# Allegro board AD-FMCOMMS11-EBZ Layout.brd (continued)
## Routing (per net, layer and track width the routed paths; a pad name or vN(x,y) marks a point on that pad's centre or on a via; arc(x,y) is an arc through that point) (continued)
UNNAMED_22_CAP_I380_N1: length 4.2
  BOTTOM w0.203: R89.2 C71.1 51.55,34.89 53.21,34.89 53.49,34.61 Q4.4
UNNAMED_22_CAP_I380_N2: length 5.3
  BOTTOM w0.305: 53.85,33.24 52.2,33.24 C71.2
  BOTTOM w0.406: 54.81,33.49 Q4.2 ; 55.47,33.49 Q4.1 ; 54.15,33.49 Q4.3
UNNAMED_23_AD9625_I119_SYSREF: length 1
  TOP w0.254: U101.K14 v1(55.21,56.09)
  BOTTOM w0.254: v1(55.21,56.09) 55.24,56.06 C105.1
UNNAMED_23_AD9625_I119_SYSREF_1: length 1.1
  TOP w0.254: U101.J14 v1(54.41,56.04)
  BOTTOM w0.254: v1(54.41,56.04) 54.48,55.97 C141.1
UNNAMED_25_ADHMC1119_I179_ATTIN: length 0.3
  TOP w0.686: 25.98,50.63 C323.2
UNNAMED_25_ADHMC1119_I179_ATTOU: length 1.7
  TOP w0.203: C324.1 32.69,50.64 U25.14
UNNAMED_25_ADHMC1119_I179_P: length 1.5
  TOP w0.254: R137.2 26.19,52.22 26.77,51.65 U25.3
UNNAMED_25_CAP_I165_N1: length 1.9
  TOP w0.203: C318.1 40.51,51.22 40,50.71 T5.6
UNNAMED_25_CAP_I165_N2: length 0.8
  TOP w0.203: R57.1 C318.2
UNNAMED_25_CAP_I166_N1: length 1.9
  TOP w0.203: T5.4 40,53.25 40.51,52.74 C319.1
UNNAMED_25_CAP_I166_N2: length 0.8
  TOP w0.203: R58.1 C319.2
UNNAMED_25_CAP_I167_N2: length 3.9
  TOP w0.203: 43.74,51.98 43.74,52.09 R60.1 ; 43.74,51.98 43.74,51.87 R59.2 ; 43.74,51.98 C320.2 ; 43.74,51.98 43.87,51.98 ; R59.2 44.15,51.87 44.15,51.98 ; R59.2 43.94,51.9 ; R60.1 44.15,52.09 44.15,51.98 ; R60.1 43.94,51.9 ; 43.94,51.9 43.87,51.98 ; 44.15,51.98 R61.1 ; 44.15,51.98 43.87,51.98
UNNAMED_25_CAP_I186_N2: length 3.1
  TOP w0.203: T5.1 36.31,50.63 C324.2
UNNAMED_25_CAP_I188_N1: length 23.4
  TOP w0.686: J6.1 C323.1
UNNAMED_25_RES_I158_N1: length 1.6
  TOP w0.203: R62.1 44.32,51.03 R59.1 43.75,51.22 R57.2
UNNAMED_25_RES_I159_N2: length 1.7
  TOP w0.203: R58.2 43.75,52.74 R60.2 44.45,52.93 R63.1
UNNAMED_26_ADM7154_I174_BYP: length 1.9
  TOP w0.203: v3(62.99,35.52) 63.37,35.65 U20.3
  BOTTOM w0.305: v3(62.99,35.52) 62.99,36.27 C245.2
UNNAMED_26_ADM7154_I174_REF: length 2.9
  TOP w0.203: 68.17,35.15 C248.1 ; 68.17,35.15 68.17,35.29 67.81,35.65 U20.6 ; 68.17,35.15 U20.5
UNNAMED_26_ADM7154_I174_VOUT: length 8.7
  TOP w0.305: U20.2 63,36.15
  TOP w0.635: 55.88,34.53 E29.1 56.87,35.46 ; 58.93,34.53 E28.1 ; E28.1 59.92,35.46 ; E28.1 57.94,35.46
  TOP w0.762: 60.9,36.37 C250.1 ; C250.1 62.8,36.37 ; C250.1 61.85,37.27
UNNAMED_26_ADM7154_I174_VREG: length 2.3
  TOP w0.305: U20.1 64.08,38.66 C247.1
UNNAMED_26_ADP1741_I5_ADJ: length 3.1
  TOP w0.203: v3(80.64,64.98) 81.07,64.56 VR2.9
  BOTTOM w0.203: R119.1 v3(80.64,64.98) 80.66,65 R114.1
UNNAMED_26_ADP1741_I5_PG: length 4.3
  TOP w0.203: VR2.5 84.67,66.53 85.03,66.89 R75.2 86.93,66.13 R120.2
UNNAMED_26_ADP1741_I5_SS: length 1.6
  TOP w0.203: C226.1 83.37,66.52 VR2.7
UNNAMED_26_ADP1741_I5_VOUT: length 11
  TOP w0.305: 82.18,61.69 VR2.13 82.72,60.81 ; 80.92,62.61 VR2.12 81.79,62.08 ; 83.37,60.81 VR2.14 ; 80.92,63.91 VR2.10 ; 80.92,63.26 VR2.11
  TOP w0.635: C228.1 79.88,62.04 ; C228.1 80.84,61.14 ; C228.1 78.93,61.14 ; 79.44,63.1 E23.1 80.37,64.1
  BOTTOM w0.305: v3(80.64,62.32) R119.2
UNNAMED_26_ADP1741_I121_ADJ: length 3.3
  TOP w0.203: v3(73.66,59.4) R117.1 R113.1
  BOTTOM w0.305: VR1.9 73.24,59.56 73.41,59.4 v3(73.66,59.4)
UNNAMED_26_ADP1741_I121_PG: length 2.9
  BOTTOM w0.203: R72.2 76.33,64.29 R118.2
  BOTTOM w0.305: VR1.5 75.02,63.29 75.56,63.84 R118.2
UNNAMED_26_ADP1741_I121_SS: length 1.4
  BOTTOM w0.203: VR1.7 75.56,61.99 C207.1
UNNAMED_26_ADP1741_I121_VOUT: length 9.9
  TOP w0.508: R117.2 v3(70.74,59.4)
  BOTTOM w0.635: C227.1 71.95,58.22 ; C227.1 70.99,59.12 ; C227.1 70.04,58.22
  BOTTOM w0.762: 68.39,60.51 E24.1 69.32,59.52
  BOTTOM w1.016: E25.1 E24.1
UNNAMED_26_ADP1741_I139_ADJ: length 2.7
  TOP w0.305: R122.1 R121.1 37.34,47.57 v3(37.33,47.58)
  BOTTOM w0.203: VR3.9 v3(37.33,47.58)
UNNAMED_26_ADP1741_I139_PG: length 2.9
  BOTTOM w0.203: 34.46,49.31 34.28,49.49 34.29,49.5 R76.2 ; 34.46,49.31 34.46,49.31 R126.2 ; 34.46,49.31 VR3.5
UNNAMED_26_ADP1741_I139_SS: length 1.7
  BOTTOM w0.203: C246.1 35.75,47.84 VR3.7
UNNAMED_26_ADP1741_I139_VOUT: length 10.6
  TOP w0.305: R122.2 38.48,44.66 v3(38.23,44.41)
  BOTTOM w0.305: 36.94,44.03 VR3.13 36.41,43.16 ; VR3.11 38.21,45.61 ; 38.21,44.96 VR3.12 37.33,44.43 ; VR3.10 38.21,46.26 ; 35.76,43.16 VR3.14
  BOTTOM w0.635: 38.42,45.85 C249.1 39.37,44.94
  BOTTOM w0.762: 39.31,44.39 E30.1 38.38,43.39
UNNAMED_27_CAP_I362_N2: length 2.1
  TOP w0.254: v1(98.37,57.29) 98.37,56.77 98.11,56.51 97.64,56.51 C208.2
  BOTTOM w0.254: P1.A2 v1(98.37,57.29)
UNNAMED_27_CAP_I363_N2: length 3
  TOP w0.254: v1(99.08,57.29) 98.82,57.04 98.82,56.58 98.3,56.06 97.64,56.06 C209.2
  BOTTOM w0.254: P1.A3 v1(99.08,57.29)
UNNAMED_27_CAP_I364_N2: length 3.2
  TOP w0.254: C211.2 97.64,50.72 98.23,50.72 98.93,51.41 98.93,52.06 v1(99.08,52.21)
  BOTTOM w0.254: P1.A7 v1(99.08,52.21)
UNNAMED_27_CAP_I365_N2: length 2.4
  TOP w0.254: v1(98.37,52.21) 98.47,52.11 98.47,51.6 98.04,51.18 97.64,51.18 C210.2
  BOTTOM w0.254: P1.A6 v1(98.37,52.21)
UNNAMED_27_CAP_I366_N2: length 3.2
  TOP w0.254: v1(99.08,47.13) 98.82,46.88 98.82,46.21 98.26,45.64 97.64,45.64 C213.2
  BOTTOM w0.254: P1.A11 v1(99.08,47.13)
UNNAMED_27_CAP_I367_N2: length 2.4
  TOP w0.254: v1(98.37,47.13) 98.37,46.4 98.07,46.1 97.64,46.1 C212.2
  BOTTOM w0.254: P1.A10 v1(98.37,47.13)
UNNAMED_27_CAP_I368_N2: length 2.5
  TOP w0.254: v1(98.37,42.05) 98.5,41.92 98.5,41.45 98.07,41.02 97.64,41.02 C214.2
  BOTTOM w0.254: P1.A14 v1(98.37,42.05)
UNNAMED_27_CAP_I369_N2: length 3.2
  TOP w0.254: v1(99.08,42.05) 98.96,41.93 98.96,41.26 98.26,40.56 97.64,40.56 C215.2
  BOTTOM w0.254: P1.A15 v1(99.08,42.05)
UNNAMED_27_CAP_I370_N2: length 2.4
  TOP w0.254: C216.2 97.64,35.94 98.07,35.94 98.37,36.24 v1(98.37,36.97)
  BOTTOM w0.254: P1.A18 v1(98.37,36.97)
UNNAMED_27_CAP_I371_N2: length 3.2
  TOP w0.254: C217.2 97.64,35.48 98.26,35.48 98.82,36.05 98.82,36.72 v1(99.08,36.97)
  BOTTOM w0.254: P1.A19 v1(99.08,36.97)
UNNAMED_27_CAP_I373_N2: length 3.2
  TOP w0.254: v1(97.81,44.59) 97.55,44.34 97.55,43.77 96.89,43.1 96.37,43.1 C219.2
  BOTTOM w0.254: P1.B13 v1(97.81,44.59)
UNNAMED_27_CAP_I374_N2: length 2.3
  TOP w0.254: C218.2 96.37,43.56 96.7,43.56 97.1,43.96 v1(97.1,44.59)
  BOTTOM w0.254: P1.B12 v1(97.1,44.59)
UNNAMED_27_CAP_I375_N2: length 2.4
  TOP w0.254: C220.2 96.37,38.48 96.8,38.48 97.1,38.78 v1(97.1,39.51)
  BOTTOM w0.254: P1.B16 v1(97.1,39.51)
UNNAMED_27_CAP_I376_N2: length 3.2
  TOP w0.254: C221.2 96.37,38.02 96.99,38.02 97.55,38.59 97.55,39.26 v1(97.81,39.51)
  BOTTOM w0.254: P1.B17 v1(97.81,39.51)
UNNAMED_27_CAP_I377_N2: length 3.5
  TOP w0.254: C223.2 97.28,53.97 96.7,53.97 96.08,53.36 96.08,52.47 v1(95.83,52.21)
  BOTTOM w0.254: P1.C7 v1(95.83,52.21)
UNNAMED_27_CAP_I378_N2: length 2.6
  TOP w0.254: C222.2 97.28,53.52 96.89,53.52 96.54,53.17 v1(96.54,52.21)
  BOTTOM w0.254: P1.C6 v1(96.54,52.21)
UNNAMED_27_CAP_I461_N2: length 2.6
  TOP w0.254: v1(98.37,31.89) 98.5,31.76 98.5,31.13 98.21,30.83 97.64,30.83 C165.2
  BOTTOM w0.254: P1.A22 v1(98.37,31.89)
UNNAMED_27_CAP_I462_N2: length 3.3
  TOP w0.254: v1(99.08,31.89) 98.96,31.77 98.96,30.94 98.4,30.38 97.64,30.38 C166.2
  BOTTOM w0.254: P1.A23 v1(99.08,31.89)
UNNAMED_27_CAP_I463_N2: length 1.5
  TOP w0.254: C167.2 98.71,21.95 99.24,21.95 v1(99.38,22.09)
  BOTTOM w0.254: P1.A30 v1(99.38,22.09)
UNNAMED_27_CAP_I464_N2: length 1.5
  TOP w0.254: v1(99.38,21.38) 99.27,21.49 98.71,21.49 C168.2
  BOTTOM w0.254: P1.A31 v1(99.38,21.38)
UNNAMED_27_CAP_I465_N2: length 2.9
  TOP w0.254: v1(97.1,14.11) 97.35,14.37 97.35,14.77 96.95,15.18 96.13,15.18 C179.2
  BOTTOM w0.254: 97.45,14.75 v1(97.1,14.11)
UNNAMED_27_CAP_I466_N2: length 3.6
  TOP w0.254: v1(97.81,14.11) 97.81,14.96 97.13,15.64 96.13,15.64 C180.2
  BOTTOM w0.254: 97.45,13.48 v1(97.81,14.11)
UNNAMED_27_CAP_I467_N2: length 2.9
  TOP w0.254: v1(98.37,11.57) 98.62,11.83 98.62,12.23 98.22,12.64 97.4,12.64 C169.2
  BOTTOM w0.254: P1.A38 v1(98.37,11.57)
UNNAMED_27_CAP_I468_N2: length 3.6
  TOP w0.254: C170.2 97.4,13.1 98.4,13.1 99.08,12.42 v1(99.08,11.57)
  BOTTOM w0.254: P1.A39 v1(99.08,11.57)
UNNAMED_27_CAP_I469_N2: length 2.7
  TOP w0.254: v1(97.1,19.19) 97.33,19.42 97.33,19.6 96.86,20.07 96.09,20.07 C171.2
  BOTTOM w0.254: 97.45,19.83 v1(97.1,19.19)
UNNAMED_27_CAP_I470_N2: length 3.4
  TOP w0.254: C172.2 96.08,20.53 97.05,20.53 97.78,19.79 97.78,19.24 97.81,19.21 v1(97.81,19.19)
  BOTTOM w0.254: 97.45,18.56 v1(97.81,19.19)
UNNAMED_27_CAP_I471_N2: length 2.8
  TOP w0.254: v1(98.37,16.65) 98.6,16.88 98.6,17.06 97.77,17.89 97.4,17.89 C177.2
  BOTTOM w0.254: P1.A34 v1(98.37,16.65)
UNNAMED_27_CAP_I472_N2: length 3.5
  TOP w0.254: C178.2 97.4,18.34 97.96,18.34 99.05,17.25 99.05,16.7 99.08,16.67 v1(99.08,16.65)
  BOTTOM w0.254: P1.A35 v1(99.08,16.65)
UNNAMED_27_CAP_I473_N2: length 1.4
  TOP w0.254: C176.2 98.77,26.57 99.27,26.57 v1(99.38,26.46)
  BOTTOM w0.254: P1.A27 v1(99.38,26.46)
UNNAMED_27_CAP_I474_N2: length 1.4
  TOP w0.254: C175.2 98.77,27.03 99.24,27.03 v1(99.38,27.17)
  BOTTOM w0.254: P1.A26 v1(99.38,27.17)
UNNAMED_27_CAP_I475_N2: length 13.4
  BOTTOM w0.254: P1.C3 96.18,56.65 95.62,56.09 86.92,56.09 86.58,56.43 85.04,56.43 84.32,55.71 84.32,55.13 84.5,54.96 C174.2
UNNAMED_27_CAP_I476_N2: length 14.2
  BOTTOM w0.254: C173.2 83.86,55.9 84.85,56.89 86.64,56.89 87.11,57.36 95.62,57.36 96.18,57.92 P1.C2
UNNAMED_27_CAP_I499_N2: length 2.4
  TOP w0.127: v1(94.56,54.75) 94.74,54.57 94.74,53.94 94.6,53.8 94.25,53.8 94.24,53.81 94.23,53.81 C239.2
  BOTTOM w0.127: P1.D4 v1(94.56,54.75)
UNNAMED_27_CAP_I500_N2: length 2.8
  TOP w0.127: C240.2 94.25,53.54 94.71,53.54 95,53.83 95,54.48 v1(95.27,54.75)
  BOTTOM w0.127: P1.D5 v1(95.27,54.75)
UNNAMED_27_CAP_I501_N2: length 3.7
  TOP w0.127: v1(97.92,34.38) 97.59,34.05 97.59,33.61 97.16,33.18 96.04,33.18 C32.2
  BOTTOM w0.127: 97.45,35.07 v1(97.92,34.38)
UNNAMED_27_CAP_I502_N2: length 3.2
  TOP w0.127: C34.2 95.88,33.62 96.06,33.44 97.05,33.44 97.33,33.72 97.33,34.07 v1(97.03,34.38)
  BOTTOM w0.127: 97.45,33.8 97.03,34.36 v1(97.03,34.38)
UNNAMED_27_CN400PAKV2_I437_TDI: length 1.3
  BOTTOM w0.254: 94.91,22.37 94.91,21.1
UNNAMED_27_CN400PAKV2_I439_LA03: length 4
  TOP w0.127: R81.2 88.87,49.25 89.07,49.44 90.8,49.44 90.93,49.31 90.93,48.59 v1(90.75,48.4)
  BOTTOM w0.127: P1.G10 v1(90.75,48.4)
UNNAMED_27_CN400PAKV2_I439_LA_1: length 4.3
  TOP w0.127: v1(91.46,48.4) 91.19,48.68 91.19,49.42 90.91,49.69 89.01,49.69 R80.2
  BOTTOM w0.127: P1.G9 v1(91.46,48.4)
UNNAMED_28_ADF4355_I1290_CPOUT: length 3.7
  BOTTOM w0.203: U18.7 39.35,38.55 39.76,38.96 C75.1 C76.1 R140.1
UNNAMED_28_ADF4355_I1290_CREG1: length 2.7
  BOTTOM w0.203: C25.1 34.92,33.36 35.33,33.77 U18.25
UNNAMED_28_ADF4355_I1290_CREG2: length 1.7
  BOTTOM w0.305: C30.1 34.14,37.27 U18.32
UNNAMED_28_ADF4355_I1290_RFOU_1: length 5.5
  BOTTOM w0.127: 44.32,36.92 45.21,36.92 C242.1 ; 44.32,36.92 L13.1 ; 44.32,36.92 43.03,36.92 42.01,35.89 41.25,35.89 41.13,35.77 U18.12
UNNAMED_28_ADF4355_I1290_RFOU_2: length 8
  BOTTOM w0.127: 44.53,30.36 44.8,30.09 C11.1 ; 44.53,30.36 44.37,30.52 ; 44.53,30.36 44.37,30.36 ; 44.37,30.52 43.31,31.58 43.31,33.51 42.3,34.52 41.37,34.52 41.13,34.27 U18.15 ; 44.37,30.52 44.37,30.36 ; L16.1 44.37,30.36
UNNAMED_28_ADF4355_I1290_RFOUTA: length 5.5
  BOTTOM w0.127: 44.32,37.17 42.93,37.17 41.9,36.15 41.25,36.15 41.13,36.27 U18.11 ; 44.32,37.17 45.24,37.17 C265.1 ; 44.32,37.17 L14.1
UNNAMED_28_ADF4355_I1290_RFOUTB: length 8.1
  BOTTOM w0.127: 44.71,30.7 44.71,30.54 ; 44.71,30.7 L15.1 ; 44.71,30.7 44.55,30.7 ; 44.71,30.54 44.71,30.54 44.97,30.28 C12.1 ; 44.71,30.54 44.55,30.7 ; 44.55,30.7 43.56,31.69 43.56,33.62 42.41,34.77 U18.14
UNNAMED_28_ADF4355_I1290_RSET: length 2.3
  TOP w0.203: v1(37.85,32.04) 37.85,32.84 R9.2
  BOTTOM w0.203: v1(37.85,32.04) 37.57,32.04 37.35,32.26 U18.22
UNNAMED_28_ADF4355_I1290_VBIAS: length 3.5
  BOTTOM w0.203: U18.24 36.35,32 C14.1 35.88,31.72 35.61,31.46 35.61,30.68 C81.1
UNNAMED_28_ADF4355_I1290_VREF: length 3.4
  BOTTOM w0.203: C4.1 37.54,30.68 37.54,31.46 37.27,31.72 C5.1 36.85,31.96 U18.23
UNNAMED_28_CAP_I1241_N1: length 5.3
  TOP w0.203: C127.1 57.47,65.09 R37.1 58.08,64.48 J2.1
UNNAMED_28_CAP_I1241_N2: length 2.6
  TOP w0.203: T3.3 54.58,66.38 55.14,65.82 55.46,65.82 C127.2
UNNAMED_28_CAP_I1252_N1: length 4.3
  TOP w0.203: C204.1 J3.1
UNNAMED_28_CAP_I1252_N2: length 3.1
  TOP w0.203: C204.2 50.67,4.79 51.1,4.35 T4.3
UNNAMED_28_CAP_I1268_N1: length 1.8
  TOP w0.203: JP3.2 51.18,59.26 C202.1
UNNAMED_28_CAP_I1269_N1: length 1.8
  TOP w0.203: JP4.2 53.7,59.29 C201.1
UNNAMED_28_CAP_I1272_N2: length 2.6
  TOP w0.305: 52.07,57.24 R69.2 ; 52.07,57.24 52.41,57.58 ; 52.07,57.24 52.76,57.24 ; 52.76,57.24 52.41,57.58 ; 52.76,57.24 R70.1 ; 52.41,57.58 C203.2
UNNAMED_28_CAP_I1301_N1: length 4.2
  TOP w0.203: C190.1 51.79,13.93 C188.1 51.79,12.24 JP22.2
UNNAMED_28_CAP_I1302_N1: length 4.2
  TOP w0.203: C191.1 51.16,13.93 C189.1 51.16,12.31 JP5.2
UNNAMED_28_CAP_I1313_N1: length 5
  BOTTOM w0.127: C187.1 33.53,35.84 R8.1 32.75,35.7 29.54,35.7 29.41,35.82 JP1.2
UNNAMED_28_CAP_I1314_N1: length 5.1
  BOTTOM w0.127: JP2.2 29.41,35.27 29.54,35.39 32.7,35.39 R8.2 33.53,35.2 C186.1
UNNAMED_28_CAP_I1349_N2: length 1.4
  BOTTOM w0.203: R94.1 C76.2
UNNAMED_28_CAP_I1359_N2: length 27.3
  TOP w0.203: v1(51.87,8.72) JP22.1
  BOTTOM w0.127: v1(51.87,8.72) 51.03,8.72 50.8,8.95 50.8,9.44 50.37,9.87 47.22,9.87 46.61,10.48 46.61,28.78 45.62,29.77 C12.2
UNNAMED_28_CAP_I1360_N2: length 27.4
  TOP w0.203: JP5.1 v1(49.28,8.72)
  BOTTOM w0.127: C11.2 45.57,29.46 46.35,28.68 46.35,10.37 47.12,9.61 50.27,9.61 50.55,9.33 50.55,8.98 50.29,8.72 v1(49.28,8.72)
UNNAMED_28_CAP_I1372_N2: length 22.6
  BOTTOM w0.127: U19.5 45.47,55.71 44.83,55.08 44.64,55.08 44.37,54.81 44.37,51.37 46.23,49.52 46.23,43.6 47.68,42.15 47.68,37.48 47.12,36.92 46.08,36.92 C242.2
UNNAMED_28_CAP_I1373_N2: length 22.6
  BOTTOM w0.127: U19.7 42.93,55.66 43.51,55.08 43.81,55.08 44.12,54.77 44.12,51.26 45.97,49.41 45.97,43.5 47.42,42.05 47.42,39.21 47.22,39 47.22,38.8 47.42,38.6 47.42,38.39 47.22,38.19 47.22,37.99 47.42,37.78 47.42,37.58 47.01,37.17 46.05,37.17 C265.2
UNNAMED_28_CAP_I1380_N1: length 4.4
  TOP w0.203: C41.1 J7.1
UNNAMED_28_CAP_I1380_N2: length 3.7
  TOP w0.203: C41.2 17.78,34.38 18.54,35.14 T6.3
UNNAMED_28_CNBNC3P_I1213_CNTR: length 5
  TOP w0.203: J1.1 v3(16.26,43.14)
  BOTTOM w0.203: v3(16.26,43.14) T2.1
UNNAMED_28_DIOLED_I1378_P: length 2
  TOP w0.203: DS1.A 33.26,46.06 R11.1
UNNAMED_28_HMC361_I1297_OUT: length 15.9
  TOP w0.203: JP3.3 49.42,61.06 v3(50.04,61.68)
  BOTTOM w0.127: v3(50.04,61.68) 51.31,61.68 51.82,62.19 51.82,62.85 50.57,64.1 43.41,64.1 43.05,63.74 43.05,63.08 43.31,62.83 43.94,62.83 44.2,62.57 U19.3
UNNAMED_28_HMC361_I1297_OUTN: length 16
  TOP w0.203: v3(53.04,61.6) 53.55,61.09 JP4.3
  BOTTOM w0.127: U19.1 41.66,62.57 41.91,62.83 42.54,62.83 42.8,63.08 42.8,63.84 43.31,64.35 50.67,64.35 52.07,62.95 52.07,62.06 52.53,61.6 v3(53.04,61.6)
UNNAMED_28_NC3PJMPR_I1233_B: length 2.7
  TOP w0.203: JP5.3 51.1,8.78 T4.4
UNNAMED_28_NC3PJMPR_I1234_A: length 3
  TOP w0.203: JP3.1 52.04,61.93 T3.6
UNNAMED_28_NC3PJMPR_I1235_A: length 3
  TOP w0.203: JP4.1 54.58,61.95 T3.4
UNNAMED_28_NC3PJMPR_I1280_B: length 2.7
  TOP w0.203: JP22.3 53.64,8.76 T4.6
UNNAMED_28_NC3PJMPR_I1389_B: length 23.1
  L3_SIGNAL w0.127: v3(30.99,36.54) 30.99,35.77 30.86,35.65 29.72,35.65 27.69,37.68 23.24,37.68 22.54,38.38 19.2,38.38 18.95,38.13 v3(18.61,38.13)
  BOTTOM w0.127: T2.5 16.26,37.3 16,37.04 15.37,37.04 15.11,36.79 15.11,36.28 15.37,36.03 16.81,36.03 16.99,36.21 16.99,36.57 17.17,36.75 17.53,36.75 17.71,36.93 17.71,37.29 17.89,37.47 18.25,37.47 18.61,37.82 v3(18.61,38.13) ; JP1.3 v3(30.99,36.54)
UNNAMED_28_NC3PJMPR_I1390_B: length 23.1
  L3_SIGNAL w0.127: v3(19.18,37.68) 19.18,38 19.3,38.12 22.44,38.12 23.14,37.43 27.58,37.43 29.61,35.39 30.86,35.39 30.99,35.27 v3(30.99,34.5)
  BOTTOM w0.127: v3(19.18,37.68) 18.82,37.68 16.92,35.77 15.26,35.77 14.86,36.18 14.86,36.79 14.6,37.04 13.97,37.04 13.72,37.3 T2.4 ; v3(30.99,34.5) JP2.3
UNNAMED_29_ADM7150_I83_BYP: length 2.3
  TOP w0.305: U12.3 28.79,41.36 C143.1
UNNAMED_29_ADM7150_I83_REF: length 2.8
  TOP w0.203: C146.1 24.03,41.86 24.38,41.86 ; 24.38,41.86 U12.5 ; 24.38,41.86 24.38,41.5 24.53,41.36 U12.6
UNNAMED_29_ADM7150_I83_VOUT: length 4.6
  TOP w0.305: C147.1 29.42,40.86 U12.2
  TOP w0.762: C147.1 30.52,41.11 31.56,41.11 E17.1
UNNAMED_29_ADM7150_I83_VREG: length 2.3
  TOP w0.305: U12.1 27.99,39.78 28.45,39.33 28.45,38.43 C145.1
UNNAMED_29_ADM7170_I32_SENSE: length 8.6
  TOP w0.305: 27.99,27.78 U15.1 28.77,28.29 ; U15.3 28.77,29.29 ; U15.2 28.77,28.79
  TOP w0.635: 29.49,30.44 E18.1 ; E18.1 30.42,31.43 ; E18.1 30.42,29.45 ; 29.02,27.99 C148.1 ; C148.1 29.97,28.89 ; C148.1 30.93,27.99
UNNAMED_29_ADM7170_I92_SENSE: length 9.3
  TOP w0.305: U17.2 35.17,66.03 ; 35.17,66.03 34.68,65.53 U17.3 ; 35.17,66.03 C150.1 35.68,65.72 U17.1
  TOP w1.016: C150.1 E22.1
UNNAMED_30_AD7291_I369_DCAP: length 2.2
  TOP w0.305: U26.8 104.52,17.02 C128.2
UNNAMED_30_AD7291_I369_VIN0: length 38.5
  TOP w0.203: R56.2 v3(101.47,8.85) 102.36,9.74 104.19,9.74 104.52,10.07 U26.18
  L10_SIGNAL w0.203: v3(101.47,8.85) 99.82,8.85 99,9.67 87.67,9.67 85.77,11.57 85.77,14.9 80.9,19.77 v3(80.9,24.73)
  BOTTOM w0.203: v3(80.9,24.73) 80.9,25.5 R55.1
UNNAMED_30_AD7291_I369_VIN1: length 12.6
  TOP w0.203: R40.1 v3(96.27,8.09) ; U26.19 105.02,9.99 104.39,9.36 103.25,9.36 v3(102.74,8.85) R47.2
  L3_SIGNAL w0.203: v3(96.27,8.09) 101.98,8.09 v3(102.74,8.85)
UNNAMED_30_AD7291_I369_VIN2: length 19.6
  TOP w0.203: R35.2 v3(104.01,8.85) 104.52,8.85 105.52,9.85 U26.20
  TOP w0.305: R34.1 v3(101.78,22.11)
  BOTTOM w0.305: v3(104.01,8.85) 103.34,9.52 103.09,9.52 102.11,10.5 102.11,20.92 101.78,21.24 v3(101.78,22.11)
UNNAMED_30_AD7291_I369_VIN3: length 65
  TOP w0.203: U26.1 106.54,10.11 v3(105.28,8.85) R38.2 ; v3(75.56,38.57) 75.56,41.1 R36.1
  L3_SIGNAL w0.203: v3(105.28,8.85) 104.59,9.54 86.16,9.54 v3(85.6,8.98)
  L10_SIGNAL w0.203: v3(85.6,8.98) 78.87,15.71 78.87,26.5 80.77,28.41 80.77,35.9 79.38,37.3 76.83,37.3 v3(75.56,38.57)
UNNAMED_30_AD7291_I369_VIN4: length 122.5
  TOP w0.203: R50.1 v3(22.86,30.94) ; R51.2 v3(106.55,8.85) 107.44,9.74 107.44,12.59 107.24,12.79 U26.2
  L3_SIGNAL w0.203: v3(106.55,8.85) 104.78,7.07 100.97,7.07 99.64,5.74 88.97,5.74 88.14,4.91 83.82,4.91 83.19,5.55 77.22,5.55 74.93,3.26 70.1,3.26 66.8,6.56 45.34,6.56 42.29,3.52 35.18,3.52 33.02,1.36 30.04,1.36 v3(29.53,1.87)
  L10_SIGNAL w0.203: v3(22.86,30.94) 22.65,30.73 22.65,10.84 28.29,5.2 28.29,3.1 v3(29.53,1.87)
UNNAMED_30_AD7291_I369_VIN6: length 57.5
  TOP w0.203: R65.2 63.75,1.87 64.01,2.12 65.41,2.12 68.22,4.94 80.11,4.94 81.53,3.52 v3(82.55,3.52) ; R64.1 v3(105.28,5.29) 105.79,5.8 106.81,5.8 108.08,7.07 108.08,13.5 107.78,13.8 U26.4
  L3_SIGNAL w0.203: v3(82.55,3.52) 83.31,4.28 88.39,4.28 89.28,5.17 105.16,5.17 v3(105.28,5.29)
UNNAMED_30_AD7291_I369_VIN7: length 28.5
  TOP w0.203: U26.5 107.92,14.3 108.46,13.76 108.46,6.69 107.06,5.29 v3(106.55,5.29) R67.2
  TOP w0.305: R66.1 92.84,5.68 94.23,4.28 v3(94.87,4.28)
  L3_SIGNAL w0.305: v3(106.55,5.29) 105.54,4.28 v3(94.87,4.28)
UNNAMED_30_AD7291_I369_VREF: length 3.4
  TOP w0.305: U26.7 105.02,16 105.45,16.43 106.2,16.43 C156.2
VADJ_P1: length 20.6
  TOP w0.203: v3(103.63,43.65) 103.63,44.34 U24.6 ; U23.6 103.39,51.28 103.12,51.01 v3(103.12,50.51) ; U13.15 106.66,39.56 v3(107.06,39.97)
  TOP w0.254: U24.1 104.78,47.95 104.27,48.46 C97.2 ; U23.1 104.78,54.82 C94.2 ; U13.1 104.78,41.23 C90.2
  TOP w0.305: U14.1 107.43,32.23 C92.2 107.58,32.08 v3(108.2,32.08) ; C90.2 104.13,41.88 v3(104.13,42.51) ; C97.2 104.13,48.74 v3(104.13,49.36) ; R66.2 92.82,7.95 v3(91.74,9.03) ; C94.2 104.13,55.47 v3(104.13,56.09)
  BOTTOM w0.305: P1.E39 v1(93.01,10.3)
  BOTTOM w0.406: 92.37,9.67 v3(91.74,9.03) ; 87.29,9.67 86.84,10.12 v3(86.36,10.12) ; 89.83,9.67 v3(89.2,9.03) ; P1.G39 v3(90.47,11.57) ; P1.J39 v3(87.93,11.57)
VCM: length 3.8
  TOP w0.203: R61.2 v1(45.67,51.98)
  TOP w0.305: U101.A7 v1(47.61,49.98)
  BOTTOM w0.203: v1(45.67,51.98) 46.25,51.98 47.61,50.63 C197.1 47.61,49.99 v1(47.61,49.98)
VM_BYP: length 0.8
  TOP w0.305: U101.A12 v1(47.61,53.98)
  BOTTOM w0.254: v1(47.61,53.98) 47.85,53.74 C144.1
VMON: length 7.1
  TOP w0.305: U101.E5 v1(50.81,47.98)
  L3_SIGNAL w0.127: v3(50.48,42.19) 50.01,42.66 50.01,47.53 50.46,47.98 v1(50.81,47.98)
VNEG12_DAC: length 17.5
  TOP w0.305: 59.46,10.76 TP5.1 60.2,10.02
  TOP w0.508: v3(48.82,15.84) C79.2 ; 59.55,8.72 C322.1 60.21,9.38 ; R7.2 49.91,27.51 v3(49.91,28.15) ; v3(48.96,14.25) 48.96,13.77 C185.2
  TOP w0.635: 59.28,10.25 C117.2 58.38,9.29 ; C322.1 60.21,7.53 60.13,7.46 60.13,7.35 C321.1
  TOP w0.762: E21.2 C321.1
  BOTTOM w0.254: C107.2 51.27,21.3 v2(51.22,21.34) ; v2(51.22,23.34) 51.36,23.34 C8.2 ; C114.2 v2(51.82,20.53) ; C113.2 v2(51.82,19.77)
  BOTTOM w0.305: C112.2 v2(49.72,17.93) ; v2(51.22,18.84) 51.26,18.88 C110.2 51.37,19.65 C113.2 C114.2 51.5,21.17 C107.2 ; C109.2 v2(49.72,22.38)
  BOTTOM w0.508: v3(48.82,15.84) 48.82,15.11 C49.2 ; C183.2 53.86,14.44 v3(53.21,14.44) 52.57,14.44 C184.2
  vias: v2(50.22,16.84) v3(58.8,9.1) v3(59.56,9.74)
VP_BYP: length 1.2
  TOP w0.305: U101.N12 v1(58.01,54.38)
  BOTTOM w0.305: C196.1 58.1,54.29 v1(58.01,54.38)
VTUNE_4355: length 23.9
  L10_SIGNAL w0.203: v3(38.35,31.21) 38.35,30.19 38.86,29.68 42.29,29.68 44.83,32.22 44.83,38.7 42.18,41.35 v3(42.18,42.24)
  BOTTOM w0.203: R140.2 C336.1 v3(42.18,42.24) ; U18.20 v3(38.35,31.21)
VVCO5_4355: length 16.5
  TOP w0.305: C159.1 33.53,37.16 TP24.1
  TOP w0.508: 33.85,40.5 E17.2 34.77,41.49 ; C152.1 33.74,40.16 ; C152.1 33.74,38.25 ; C152.1 34.65,39.2 ; 34.05,37.3 C159.1 33.39,37.96
  BOTTOM w0.203: C326.1 v3(38.96,30.54)
  BOTTOM w0.305: C327.1 39.52,31.65 39.52,32.17 39.85,32.49 U18.17 ; C327.1 39.56,31.33 C326.1 ; C327.1 38.85,32.04 U18.19 ; v3(38.73,41.62) 38.54,41.43 C17.1 38.54,40.14 C16.1 38.99,39.7 38.99,38.88 38.85,38.74 U18.6
  vias: v3(34.42,38.06) v3(35.05,38.06)

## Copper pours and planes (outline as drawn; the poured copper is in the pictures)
12V_P1 on TOP: 22.22,64.48 20.83,64.48 20.45,64.86 16.51,64.86 16.51,67.78 20.95,67.78 22.22,66.51
12V_P1 on BOTTOM: 66.7,6.18 66.7,8.34 65.79,8.34 65.79,9.74 66.17,9.74 66.17,10.22 68.48,10.22 69.6,9.1 69.6,6.18
12V_P1 on BOTTOM: 77.09,30.95 77.09,29.93 79.88,27.14 80.39,27.14 82.3,25.23 85.47,25.23 85.47,30.57 82.17,30.57 82.17,31.96 81.53,32.6 79.63,32.6 79.38,32.35 77.6,32.35 77.6,30.95
12V_P1 on L8_POWER: 66.99,5.68 66.99,13.3 72.39,13.3 72.39,34.89 61.59,34.89 61.59,31.08 55.56,31.08 55.56,26.63 48.45,26.63 46.54,24.73 7.62,24.73 7.62,68.36 30.48,68.36 30.48,45.05 17.78,45.05 17.78,39.45 17.97,39.27 18.23,39.27 18.29,39.33 32.38,39.33 32.38,27.9 43.63,27.9 46.35,30.63 46.36,39.33 85.79,39.33 85.79,29.23 108.78,29.23 108.78,13.3 95.25,13.3 95.25,17.74 79.06,17.74 79.06,5.68
AVDD1P3_ADC on TOP: 76.2,60.79 76.2,62.7 75.18,63.71 75.18,65.11 78.11,65.11 78.11,59.4 76.45,59.4 76.45,60.54
AVDD1P3_ADC on L8_POWER: 63.69,39.97 63.69,48.48 63.5,48.66 49.59,48.66 49.59,47.65 44.26,47.65 44.26,62.89 85.79,62.89 85.79,39.97
AVDD2P5_ADC on BOTTOM: 40.64,42.76 43.69,42.76 44.32,43.39 44.32,48.47 43.89,48.91 42.54,48.91 42.54,45.05 42.29,44.79 41.02,44.79 40.64,44.41
AVDD2P5_ADC on L3_SIGNAL: 42.54,46.32 42.54,55.84 55.12,55.84 55.12,49.36 50.04,49.36 46.99,46.32
AVDD3P3_4355 on TOP: 31.75,27.39 31.75,31.84 35.18,31.84 35.18,27.39
AVDD3P3_4355 on L8_POWER: 33.02,28.54 33.02,39.33 45.73,39.33 45.72,30.89 43.37,28.54
DVDD1P3_ADC on BOTTOM: 67.06,53.55 63.25,53.55 63.25,57.11 67.06,57.11
DVDD1P3_ADC on L5_POWER: 46.04,43.78 46.04,68.36 67.31,68.36 67.31,43.78
DVDD2P5_ADC on TOP: 55.12,36.79 57.15,36.79 57.15,43.39 54.99,43.39 54.99,40.6 55.12,40.47
DVDD2P5_ADC on L8_POWER: 86.42,29.87 86.42,63.52 43.62,63.52 43.62,47.2 43.81,47.01 50.23,47.01 50.23,48.03 63.06,48.03 63.06,39.97 46.05,39.97 45.92,39.97 18.41,39.97 18.41,44.41 31.11,44.41 31.11,68.36 108.78,68.36 108.78,29.87
DVDD2P5_ADC on L10_SIGNAL: 57.15,43.9 53.72,43.9 53.72,47.46 50.93,47.46 49.78,48.6 47.12,48.6 47.12,44.66 50.55,41.24 57.15,41.24
DVDD3P3_4355 on TOP: 42.16,35.01 46.35,35.01 47.75,36.41 48.51,36.41 48.51,37.55 45.47,37.55 44.7,36.79 43.05,36.79 42.16,35.9
DVDD3P3_4355 on L10_SIGNAL: 34.29,31.71 34.29,34.25 37.4,37.36 37.44,37.32 37.72,37.32 37.46,37.58 37.46,39.33 43.18,39.33 43.18,31.71
DVDD12_DAC on BOTTOM: 59.31,31.71 60.71,31.71 60.83,31.58 61.59,31.58 61.59,33.62 63.37,33.62 63.37,34.5 62.1,35.77 59.31,35.77 58.55,35.01 58.55,32.47
DVDD12_DAC on L5_POWER: 46.67,18.69 46.67,26 50.16,26 50.16,33.93 54.29,33.93 54.29,38.06 60.64,38.06 60.64,30.76 53.34,30.76 53.34,22.5 55.24,22.5 55.24,18.69
DVDDIO3P3_ADC on TOP: 49.28,37.55 49.28,34.5 50.04,34.5 50.04,32.98 51.82,32.98 52.32,33.49 52.32,36.28 51.05,37.55
DVDDIO3P3_ADC on L10_SIGNAL: 57.15,50 57.15,44.41 54.23,44.41 54.23,47.71 51.43,47.71 49.91,49.24 46.61,49.24 46.61,44.16 50.8,39.97 50.8,34.25 45.72,34.25 45.72,40.47 43.69,42.51 43.69,54.82 52.32,54.82
GND on TOP: 52.07,18.12 55.88,18.12 55.88,22.57 51.56,22.57 51.56,22.06 52.07,21.55 54.99,21.55 54.99,19.01 52.58,19.01 52.07,18.5
GND on TOP: 0.64,0.65 0.64,22.46 2.54,22.46 2.54,23.2 2.39,23.35 0.64,23.35 0.64,26.2 2.54,26.2 2.54,28.05 0.66,28.05 0.64,28.08 0.64,47.76 2.54,47.76 2.54,49.53 26.4,49.53 26.54,49.67 27.41,49.67 27.41,51.19 26.86,51.74 2.54,51.74 2.54,53.45 0.64,53.45 0.64,68.36 108.76,68.36 108.76,0.65 47.37,0.65 47.37,0.98 39.75,0.98 39.75,0.65 ; 41 cut-outs
GND on BOTTOM: 0.64,0.65 0.64,68.36 108.76,68.36 108.76,0.65 62.86,0.65 62.86,5.93 62.74,6.06 62.74,8.09 65.28,8.09 65.28,8.22 62.36,8.22 62.36,0.65 ; 71 cut-outs
GND on L2_GROUND: 0.64,0.65 0.64,24.09 17.53,24.09 17.8,23.98 17.91,23.71 18.05,23.16 18.43,22.75 18.44,22.74 18.44,22.6 19.05,21.99 19.66,22.6 19.66,22.74 19.68,22.75 20.06,23.16 20.2,23.71 19.42,25.59 17.53,26.38 0.64,26.38 0.64,49.49 25.98,49.49 26.54,49.63 26.95,50.02 27.14,50.02 27.32,50.05 27.49,50.13 27.5,50.14 27.6,50.14 27.6,50.24 27.61,50.24 27.75,50.63 27.61,51.02 27.6,51.03 27.6,51.15 27.46,51.15 27.45,51.16 27.3,51.22 27.14,51.24 26.95,51.24 26.54,51.63 25.98,51.78 0.64,51.78 0.64,68.36 108.76,68.36 108.76,0.65 ; 3 cut-outs
GND on L4_GROUND: 0.64,0.64 0.64,68.36 108.78,68.36 108.78,0.64 ; 1 cut-out
GND on L6_GROUND, L7_GROUND, L9_GROUND, L11_GROUND: 0.64,68.29 0.64,0.72 108.71,0.72 108.71,68.29
GND on L8_POWER: 0.64,0.64 0.64,68.36 6.98,68.36 6.98,24.09 27.3,24.09 27.3,10.12 36.2,10.12 36.2,0.64
SVDD12_DAC on BOTTOM: 60.07,10.25 60.07,18.88 58.93,18.88 57.4,17.36 57.4,10.25
SVDD12_DAC on L5_POWER: 46.67,14.57 46.67,18.06 55.88,18.06 55.88,23.14 53.98,23.14 53.98,26 61.28,26 61.28,14.57
VDD_1119 on TOP: 23.5,52.54 23.5,53.43 24.51,53.43 24.77,53.68 25.91,53.68 25.91,52.54
VDD_1119 on BOTTOM: 25.91,53.17 26.21,52.87 26.21,46.44 22.86,46.44 22.86,52.67 23.37,53.17
VDDA25_DAC on TOP (solid shape): 46.99,23.58 46.99,22.95 46.48,22.44 43.43,22.44 43.43,17.87 46.74,17.87 47.24,17.36 47.24,16.85 46.86,16.47 40.51,16.47 38.86,18.12 38.86,20.03 39.12,20.28 39.75,20.28 39.88,20.15 39.88,18.63 40.51,17.99 42.54,17.99 42.67,18.12 42.67,22.31 42.16,22.82 39.12,22.82 38.99,22.95 38.99,23.71 39.12,23.84 46.74,23.84
VDDA25_DAC on TOP (solid shape): 48.95,22.74 49.51,22.23 49.55,22.19 49.6,22.15 49.85,21.93 49.84,21.9 49.94,21.59 50.23,21.46 50.31,21.43 50.45,21.07 50.81,20.93 50.84,20.86 50.94,20.58 51.21,20.46 51.28,20.43 51.31,20.36 51.31,19.85 51.31,19.82 51.21,19.73 51.19,19.72 50.95,19.61 50.84,19.37 50.84,19.35 50.71,19.23 50.69,19.22 50.45,19.11 50.34,18.87 50.34,18.85 50.29,18.81 50.2,18.73 50.18,18.72 49.96,18.63 49.85,18.42 49.84,18.4 48.95,17.59 47.74,16.72 46.35,16.72 46.18,16.9 46.18,17.84 46.23,18.38 46.74,18.38 48.01,18.53 48.79,18.53 48.82,18.55 50.13,19.47 50.16,19.47 50.33,19.48 50.48,19.56 50.53,19.59 50.57,19.64 50.59,19.7 50.6,19.78 50.6,19.84 50.6,19.91 50.6,20.28 50.6,20.34 50.6,20.56 50.55,20.71 50.42,20.79 50.27,20.79 50.17,20.84 48.82,21.78 48.01,21.78 46.74,21.93 46.23,21.93 46.18,22.49 46.18,23.41 46.35,23.58 47.77,23.58
VDDA25_DAC on BOTTOM: 33.66,15.33 33.66,10.12 30.99,10.12 30.99,15.33
VDDA25_DAC on L2_GROUND: 47.57,24.22 48.59,23.2 50.16,23.2 51.94,21.42 51.94,18.88 50.29,17.23 48.26,17.23 47.5,16.47 40.51,16.47 38.86,18.12 38.86,20.41 42.04,20.41 42.54,20.92 42.54,22.06 41.91,22.69 38.73,22.69 38.73,23.96 38.99,24.22
VDDA25_DAC on L4_GROUND: 38.73,18.38 38.73,23.77 43.5,23.77 43.5,18.38
VDDA25_DAC on L8_POWER: 27.94,10.76 27.94,24.09 46.8,24.09 48.71,26 51.43,26 51.43,21.66 50.93,21.15 50.93,18.9 51.43,18.4 51.43,16.47 49.53,16.47 49.53,13.93 45.09,13.93 45.09,16.79 36.2,16.79 36.2,10.76
VDDC12_DAC on BOTTOM: 41.27,13.17 38.86,13.17 38.23,13.8 38.23,15.45 39.12,16.34 41.27,16.34
VDDC12_DAC on L8_POWER: 36.83,10.12 36.83,16.15 44.45,16.15 44.45,13.3 50.16,13.3 50.16,15.84 52.07,15.84 52.07,18.51 51.88,18.69 51.86,18.69 51.43,19.12 51.43,20.94 51.94,21.44 51.94,26 55.56,26 55.56,10.12
3P3V_P1 on TOP: 86.11,6.95 86.11,2.37 83.82,2.37 83.82,6.95
3P3V_P1 on BOTTOM: 79.76,8.98 84.71,8.98 84.71,11.01 84.07,11.64 82.04,11.64 82.04,13.42 79.38,13.42 79.38,10.37 79.76,10.37
3P3V_P1 on L8_POWER: 66.99,0.64 66.99,5.04 79.69,5.04 79.69,17.11 94.61,17.11 94.61,12.66 108.78,12.66 108.78,0.64
DAC_OUT_N on TOP (solid shape): 48.39,18.95 48.01,18.95 47.88,18.82 46.04,18.82 45.72,18.5 43.94,18.5 43.81,18.63 43.81,19.26 43.94,19.39 45.5,19.39 45.85,19.74 47.47,19.74 47.56,19.84 48.39,19.84
DAC_OUT_N on TOP (solid shape): 50.22,19.77 50.19,19.75 50.14,19.72 50.13,19.71 50.02,19.67 49.93,19.59 49.93,19.59 48.84,18.93 48.39,18.93 48.39,19.85 48.79,19.85 49.66,19.93 50.04,19.95 50.22,19.96
DAC_OUT_P on TOP (solid shape): 46.04,21.49 47.88,21.49 48.01,21.36 48.39,21.36 48.39,20.47 47.56,20.47 47.47,20.57 45.82,20.57 45.47,20.92 43.94,20.92 43.81,21.04 43.81,21.68 43.94,21.8 45.72,21.8
DAC_OUT_P on TOP (solid shape): 49.84,20.79 49.85,20.77 49.96,20.57 50.17,20.47 50.22,20.46 50.22,20.28 50.19,20.25 50.09,20.25 48.79,20.48 48.39,20.48 48.39,21.4 48.84,21.4
DRVDD1P3_ADC on BOTTOM: 67.06,58 62.99,58 62.99,61.81 65.28,61.81 66.04,61.05 67.06,61.05
DRVDD1P3_ADC on L10_SIGNAL: 52.32,62.83 52.32,55.59 57.78,50.13 57.78,44.41 60.32,44.41 60.32,51.4 57.02,54.7 57.02,58.25 65.79,58.25 65.79,62.83
DRVDD2P5_ADC on TOP: 59.69,36.79 57.66,36.79 57.66,43.39 59.31,43.39 60.2,42.51 60.2,40.98 59.69,40.47
DRVDD2P5_ADC on L10_SIGNAL: 57.78,43.9 57.78,41.24 63.25,41.24 63.25,57.75 57.53,57.75 57.53,54.82 60.83,51.52 60.83,43.9
RF_VDD_AMP_5 on TOP: 12.19,14.82 16.89,14.82 17.91,13.8 22.48,13.8 22.48,14.95 18.29,14.95 17.65,15.58 17.65,17.99 15.49,17.99 14.99,18.5 14.99,20.41 16.38,21.8 17.14,21.8 17.65,22.31 17.65,22.82 17.27,23.2 16.51,23.2 15.75,22.44 15.11,22.44 13.72,21.04 13.72,18.38 12.19,16.85
SUPPLY1P2 on BOTTOM (solid shape): 55.6,35.47 53.37,35.47 53.37,37.2 55.6,37.2
SUPPLY1P2 on TOP: 72.64,6.18 72.64,11.26 71.88,12.03 70.1,12.03 70.1,6.18
SUPPLY1P2 on BOTTOM: 52.07,37.93 52.07,35.39 56.01,35.39 56.01,37.93
SUPPLY1P2 on BOTTOM: 72.52,6.18 70.1,6.18 70.1,13.55 71.37,13.55 71.75,13.17 71.75,12.28 72.52,11.52
SUPPLY1P2 on L5_POWER: 38.73,6.31 38.73,29.17 41.91,29.17 41.91,38.06 53.66,38.06 53.66,34.57 49.53,34.57 49.53,26.63 46.04,26.63 46.04,13.93 53.02,13.93 53.02,10.12 65.72,10.12 65.72,16.47 73.03,16.47 73.03,6.31
SUPPLY1P75 on TOP: 76.83,38.7 81.41,38.7 81.41,40.35 79.63,42.12 76.83,42.12 76.83,40.85 76.45,40.47 76.45,39.08
SUPPLY1P75 on TOP: 85.22,64.1 85.22,62.44 84.96,62.19 83.95,62.19 83.95,60.16 85.34,60.16 85.85,60.67 87,60.67 88.01,61.68 88.01,64.1
SUPPLY1P75 on BOTTOM: 82.04,38.31 82.04,41.11 79.12,44.03 76.07,44.03 76.07,42.25 76.58,41.74 76.58,40.47 76.07,39.97 76.07,38.31
SUPPLY1P75 on BOTTOM: 64.52,31.58 66.29,31.58 66.47,31.41 67.56,31.41 67.56,33.11 65.15,35.52 63.37,35.52 63.37,33.49 64.52,33.49
SUPPLY1P75 on BOTTOM: 41.27,7.71 39.12,7.71 38.35,8.47 38.35,10.88 41.27,10.88
SUPPLY1P75 on BOTTOM: 70.74,62.57 68.71,62.57 68.71,66.76 72.77,66.76 72.77,63.71 70.99,63.71 70.74,63.46
SUPPLY1P75 on L5_POWER: 61.28,30.76 61.28,36.16 70.48,36.16 70.48,43.78 67.94,43.78 67.94,68.36 88.9,68.36 88.9,60.73 83.82,55.65 83.82,30.76
SUPPLY1P75 on L8_POWER: 36.83,0.64 36.83,9.49 56.2,9.49 56.2,15.2 62.23,15.2 62.23,34.25 71.75,34.25 71.75,13.93 66.36,13.93 66.36,0.64
SUPPLY3P3 on TOP: 86.61,6.95 86.61,2.37 88.77,2.37 88.77,6.95
SUPPLY3P3 on TOP: 66.55,36.03 68.45,36.03 69.6,37.17 69.6,40.6 67.06,40.6 67.06,37.55 66.55,37.04
SUPPLY3P3 on TOP: 47.12,38.31 50.67,38.31 50.67,40.98 47.5,40.98 47.12,40.6
SUPPLY3P3 on BOTTOM: 26.8,45.93 22.86,45.93 22.86,44.41 23.5,43.78 26.42,43.78 26.8,44.16
SUPPLY3P3 on BOTTOM: 32.51,42.51 30.61,44.41 30.61,46.82 32.38,46.82 32.64,47.08 34.04,47.08 34.04,44.54 35.18,44.54 35.18,42.89 34.8,42.51
SUPPLY3P3 on BOTTOM: 68.07,24.85 70.74,24.85 71.12,24.47 71.12,23.58 72.52,23.58 72.52,24.6 70.87,26.25 68.07,26.25
SUPPLY3P3 on L5_POWER: 18.1,0.64 18.1,25.36 23.5,25.36 23.5,50.76 45.4,50.76 45.4,43.14 69.85,43.14 69.85,36.79 61.28,36.79 61.28,38.7 41.91,38.7 41.91,43.14 33.21,43.14 33.02,42.95 33.02,29.17 38.1,29.17 38.1,5.86 38.29,5.68 73.66,5.68 73.66,17.11 67.31,17.11 67.31,30.12 84.45,30.12 84.45,55.39 89.53,60.47 89.53,68.36 108.78,68.36 108.78,41.87 105.41,41.87 105.41,57.11 97.34,57.11 93.98,53.75 93.98,16.47 84.45,16.47 84.45,8.85 88.27,8.85 88.27,0.64
SUPPLY5P5 on TOP: 25.91,58.51 24.26,58.51 24,58.25 14.48,58.25 14.48,55.21 23.11,55.21 23.5,55.59 25.91,55.59
SUPPLY5P5 on TOP: 3.17,14.18 3.17,11.9 6.22,11.9 6.22,14.18
SUPPLY5P5 on L5_POWER: 0.64,0.64 0.64,68.36 45.4,68.36 45.4,51.4 22.86,51.4 22.86,26 17.46,26 17.46,0.64
SUPPLYN2P8 on BOTTOM: 62.23,0.72 58.67,0.72 58.67,3.01 62.23,3.01
SVSYNC33_DAC on L8_POWER: 56.2,15.84 56.2,30.44 61.59,30.44 61.59,15.84
SW_2165 on BOTTOM: 77.34,10.37 79.12,10.37 79.12,17.87 77.22,17.87 77.22,11.77 77.34,11.64
UNNAMED_14_ADP237X_I39_SW on TOP: 24.77,64.48 26.16,64.48 27.05,65.37 31.5,65.37 31.5,67.4 31.11,67.78 26.8,67.78 26.03,67.02 26.03,64.98 25.78,64.73 24.77,64.73
UNNAMED_14_ADP238X_I1_SW1 on BOTTOM: 74.68,32.98 74.42,33.23 68.45,33.23 68.45,35.77 74.42,35.77 74.93,35.27 74.93,34 77.34,34 77.34,33.49 78.49,33.49 78.49,33.23 77.34,33.23 77.34,32.98
UNNAMED_14_ADP5073_I95_SW on BOTTOM: 64.13,10.25 61.47,10.25 59.05,7.83 59.05,6.56 62.1,6.56 62.1,8.34 62.86,9.1 64.13,9.1
UNNAMED_14_CAP_I5_N2 on BOTTOM: 75.06,36.41 68.45,36.41 68.45,40.22 72.26,44.03 75.06,44.03 75.06,42.38 74.42,41.74 74.42,40.6 75.06,39.97
UNNAMED_14_CAP_I41_N2 on TOP: 26.42,64.1 26.42,62.83 26.92,62.32 26.92,61.94 27.18,61.68 27.18,59.14 26.92,59.14 26.92,56.22 30.23,56.22 31.5,57.49 31.5,64.1
UNNAMED_14_CAP_I60_N2 on BOTTOM: 71.88,13.93 70.1,13.93 70.1,16.22 71.75,17.87 76.45,17.87 76.45,14.18 72.14,14.18
UNNAMED_14_CAP_I152_N2 on BOTTOM: 58.93,3.77 62.23,3.77 62.23,5.17 60.96,5.17 60.07,6.06 58.93,6.06
UNNAMED_22_ADM7170_I342_SENSE on TOP: 8.76,14.18 10.41,14.18 10.54,14.06 14.1,14.06 14.1,11.9 8.76,11.9
UNNAMED_22_ADP196_I267_VOUT1 on BOTTOM: 67.69,24.98 67.82,25.11 67.82,27.14 64.26,27.14 63.63,26.5 63.63,24.98
UNNAMED_22_CAP_I259_N1 on BOTTOM: 56.9,9.1 56.9,12.53 54.36,12.53 54.36,11.26 53.47,10.37 53.47,8.85 55.24,8.85 55.5,9.1
UNNAMED_22_CAP_I259_N1 on BOTTOM: 54.1,28.41 56.39,28.41 56.39,31.2 53.21,31.2 53.21,29.3
UNNAMED_22_CAP_I259_N1 on L5_POWER: 53.66,10.76 53.66,13.93 61.73,13.93 61.91,14.12 61.91,26.63 53.98,26.63 53.98,30.12 66.67,30.12 66.67,17.11 65.09,17.11 65.09,10.76
UNNAMED_22_CAP_I380_N2 on BOTTOM: 53.47,31.84 53.47,34.89 55.75,34.89 55.75,31.84
UNNAMED_26_ADM7154_I174_VOUT on TOP: 64.39,36.03 62.74,36.03 62.48,35.77 61.09,35.77 60.83,35.52 60.83,34 55.12,34 55.12,36.03 59.94,36.03 60.2,36.28 60.2,37.68 63.25,37.68 63.25,36.79 63.75,36.28 64.39,36.28
UNNAMED_26_ADP1741_I5_VOUT on TOP: 82.04,64.1 80.9,64.1 80.26,64.73 78.61,64.73 78.61,60.67 81.28,60.67 81.79,60.16 83.44,60.16 83.44,62.06 83.31,62.19 82.42,62.19 82.3,62.32 82.3,63.84
UNNAMED_26_ADP1741_I121_VOUT on BOTTOM: 67.94,58 72.14,58 72.64,58.51 72.64,60.79 70.99,60.79 70.74,61.05 70.74,62.06 68.45,62.06 67.69,61.3 67.69,58.25
UNNAMED_26_ADP1741_I139_VOUT on BOTTOM: 35.56,44.54 35.56,43.01 36.07,42.51 39.88,42.51 39.88,46.32 39.75,46.44 36.83,46.44 36.83,44.54
UNNAMED_29_ADM7170_I32_SENSE on TOP: 27.56,29.3 27.56,27.52 31.24,27.52 31.24,31.84 28.96,31.84 28.96,29.42 27.69,29.42
VADJ_P1 on L5_POWER: 88.9,0.64 88.9,9.49 85.09,9.49 85.09,15.84 94.61,15.84 94.61,53.49 97.6,56.48 104.78,56.48 104.78,41.24 108.78,41.24 108.78,0.64
VNEG12_DAC on TOP (solid shape): 50.02,22.52 50.04,22.51 50.16,22.47 50.28,22.47 50.31,22.47 50.35,22.43 50.34,22.41 50.45,22.07 50.78,21.97 50.81,21.97 50.85,21.93 50.84,21.91 50.95,21.57 51.28,21.47 51.31,21.47 51.94,20.79 51.94,19.52 51.92,19.49 51.36,18.91 51.28,18.81 51.2,18.73 51.18,18.72 50.95,18.61 50.84,18.38 50.84,18.36 50.7,18.23 50.68,18.22 50.45,18.11 50.34,17.88 50.34,17.86 50.29,17.82 50.23,17.78 49.72,17.78 49.61,17.9 49.66,18.03 50.12,18.47 50.15,18.47 50.48,18.57 50.6,18.9 50.59,18.93 50.64,18.97 50.66,18.97 50.99,19.07 51.1,19.4 51.09,19.43 51.14,19.47 51.16,19.47 51.55,19.66 51.51,20.09 51.58,20.47 51.29,20.72 51.28,20.72 51.1,20.9 51.1,20.91 50.99,21.11 50.79,21.22 50.78,21.22 50.6,21.4 50.6,21.41 50.49,21.62 50.28,21.72 50.26,21.72 50.09,21.88 49.66,22.3 49.67,22.43 49.73,22.52
VNEG12_DAC on TOP: 57.78,11.01 57.78,8.98 58.55,8.22 60.32,8.22 60.32,11.01
VNEG12_DAC on L10_SIGNAL: 46.99,7.45 46.99,29.04 52.2,29.04 52.2,15.94 53.77,14.37 53.77,12.53 59.82,12.53 59.82,7.45
VVCO5_4355 on TOP: 33.15,37.04 35.56,37.04 35.56,41.87 35.31,42.12 33.15,42.12
VVCO5_4355 on L5_POWER: 33.66,29.81 33.66,42.51 41.27,42.51 41.27,29.81

Small or netless copper shapes (teardrops, artwork), in the pictures only: 97 on TOP, 95 on BOTTOM, 72 on L3_SIGNAL, 85 on L10_SIGNAL

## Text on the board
BOTTOM: 08-042999 REV C | SECONDARY SIDE | AD-FMCOMMS11-EBZ
Board Geometry/Soldermask Bottom: 08-      -06
Ref Des/Silkscreen Bottom: 08-      -05
User.Comments: 3 | 2 | 1 | JP1 | JP3 | JP2 | JP4 | JP5 | JP22 | 4.    SOLDER PIN 1 TO PIN 2 OF JP1, JP2, JP5, AND JP22. | 5.    SOLDER PIN 2 TO PIN 3 OF JP3, AND JP4. | PIN SHORT SOLDER DETAIL | SCALE: 1:1 | SCALE: 1:3 | SCALE: 1:2.5
TOP: PRIMARY SIDE
Board Geometry/Soldermask Top: 08-      -04
Ref Des/Silkscreen Top: PLL STAT | VDDA12_DAC | DVDD12_DAC | SVSYNC33_DAC | DRVDD1P3_ADC | GND | AVDD1P3_ADC | PWR | GOOD | REF IN | SYNCB | 9508 | TX OUT | ORX IN | AUX OUT | EXT DAC CLK | EXT ADC CLK | 08-      -03
PAGE_OUTLINE: 08-      -01 | L1 PRIMARY | B | C | AS PER ECR-072917 | AS PER ECR-078924 | 23NOV17 | 31JAN19 | E. REYTA | CUSTOMER EVAL BOARD Z
DIMENSION: SEE DETAIL A | 08-      -02 | DETAIL A | DIA MAX;SEE NOTE 15 | (REF)
DISPLAY_TOP: 08-      -17
User.7: 08-      -18
User.8: 08-      -07 | L2 GROUND
User.9: 08-      -08 | L3 SIGNAL
User.11: 08-      -09 | L4 GROUND
User.12: 08-      -10 | L5 POWER
User.14: 08-      -11 | L6 GROUND
User.15: 08-      -12 | L7 GROUND
User.16: 08-      -13 | L8 POWER
User.17: 08-      -14 | L9 GROUND
User.18: CHARACTERISTIC IMPEDANCE = 50 OHMS +/- 10% | ARTWORK LINE WIDTH FOR | IMPEDANCE CONTROLLED LINES = 0.027" WITH REF PLANE L4 | 2113x1 | 3MILS | L6 GROUND PLANE   (LAYER 6) | L7 GROUND PLANE   (LAYER 7) | DIFFERENTIAL IMPEDENCE 100 OHMS +/- 10% | ARTWORK LINE WIDTH AND SPACE FOR | IMPEDANCE CONTROLLED LINES = 0.005" WIDTH/ 0.005" SPACE | IMPEDANCE CONTROLLED LINES = 0.010" WIDTH/ 0.008" SPACE
User.21: PAGE 9
User.23: 08-      -15 | L10 SIGNAL
User.24: 08-      -16 | L11 GROUND
User.29: SECONDARY SIDE | 01-
User.34: SCALE 1:1 | SCALE: 1:2.5
User.41: 3 | FIGURE | SIZE | 8.0 | PLATED | DRILL CHART: TOP to L2_GROUND | FINISHED HOLES IN MILS | QTY | 406 | DIA MAX | TOLERANCE/NOTES
User.42: DIA MAX
User.43: DIA MAX
User.44: 2
User.45: 4 | FIGURE | SIZE | 5.0 | 8.0 | 10.0 | 16.0 | 50.0 | 105.0 | 155.0 | PLATED | NON-PLATED | DRILL CHART: TOP to BOTTOM | FINISHED HOLES IN MILS | DRILL CHART: L11_GROUND to BOTTOM | QTY | 98 | 832 | 916 | 32 | 2 | 262 | TOLERANCE/NOTES | DIA MAX
